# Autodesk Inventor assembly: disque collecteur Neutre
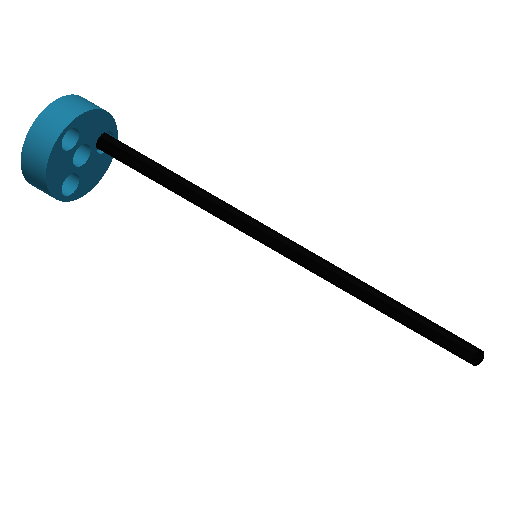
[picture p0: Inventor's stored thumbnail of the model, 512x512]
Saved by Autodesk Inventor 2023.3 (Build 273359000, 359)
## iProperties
Created: 2017-03
Part Number: disque collecteur Neutre
Document SubType Name: Assembly
Designer: thierry.jost
Author: thierry.jost
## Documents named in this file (3)
- C:\Travail\BTSTEC~1\2-TECH~1\21-Meca\214-SY~1\2141-P~1\21411-~1\214112~1\214112~2\214112~3\214112~2\DISQUE~1\20N-DI~1.IAM
- C:\Travail\BTS TechCom\2-TechnoIndus\21-Meca\214-Systémes Industriels-SI\2141-Pièces Ecrites\21411-Cycle1\214112-TP02Eolienne\2141122-DossierTechniqueEolienne\21411223-Maquette numerique\214112232-CEB-Eolienne\Disque collecteur\Disque collecteur n.ipt
- C:\Travail\BTSTEC~1\2-TECH~1\21-Meca\214-SY~1\2141-P~1\21411-~1\214112~1\214112~2\214112~3\214112~2\DISQUE~1\neutre.ipt
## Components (2 placed, 2 different names)
1. Disque collecteur n:1 — Insert:1
2. neutre:1 — Insert:1
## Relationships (1: Insert 1)
- Insert:1: Disque collecteur n:1 ↔ neutre:1
